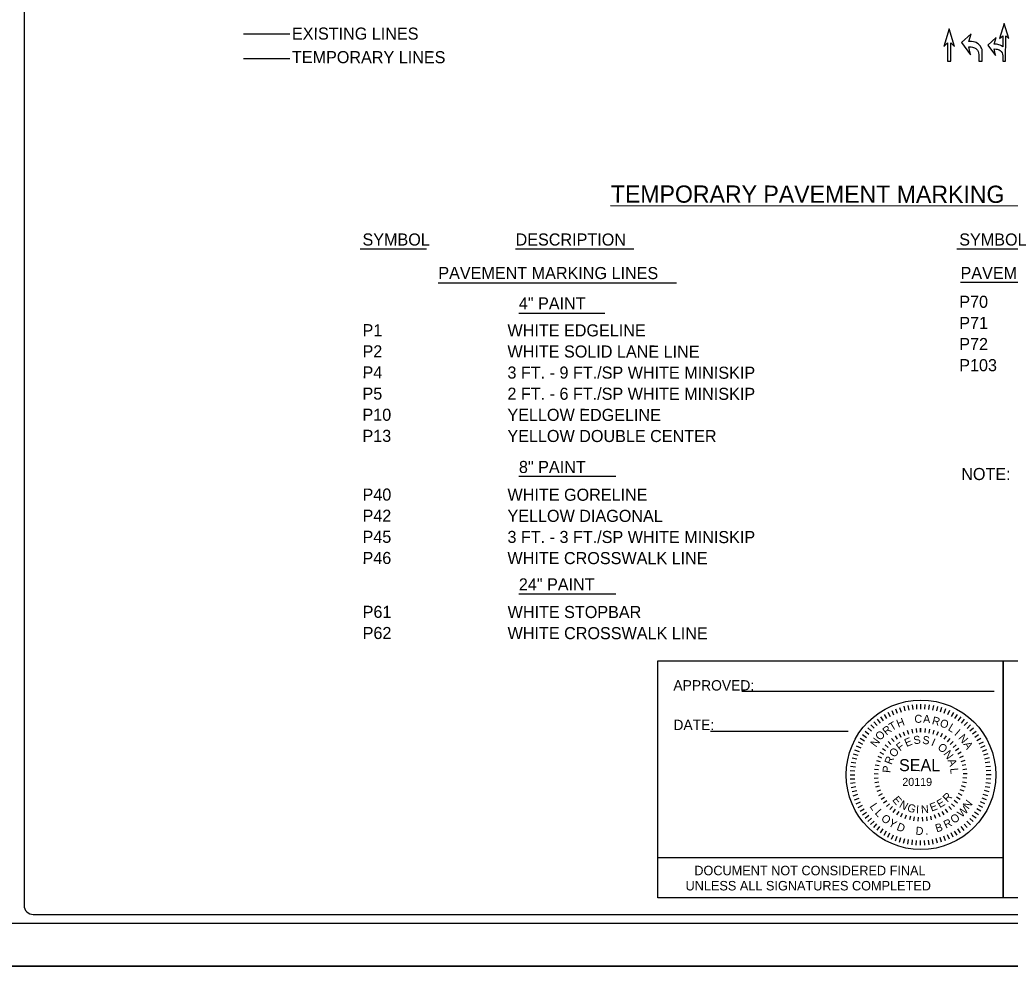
# Model space of a CAD drawing. Extents: x 1403867 to 1405555, y 486423 to 487523.
# Drawn here: x 1404600 to 1405174, y 486423 to 486971 of the extents above; entities that cross this region are included whole.
import ezdxf

# ---------------------------------------------------------------- set-up
doc = ezdxf.new("R2010")
doc.units = 0
for name, color, linetype in [('Default', 7, 'Continuous'), ('DEV BORDER CELL', 7, 'Continuous'), ('Exist Mkg Solid White Crosswalks', 7, 'Continuous'), ('Sheet Plot Border Outside CELL', 7, 'Continuous'), ('Sheet Sticker Exception Certification CELL', 7, 'Continuous')]:
    doc.layers.add(name, color=color, linetype=linetype)

msp = doc.modelspace()

# ---------------------------------------------------------------- linework, layer by layer
at = {"layer": 'Default'}
for p, q in [((1405103.41, 486569.89), (1405104.71, 486567.42)), ((1405105.64, 486570.96), (1405106.77, 486568.42)), ((1405107.92, 486571.91), (1405108.9, 486569.3)), ((1405110.25, 486572.71), (1405111.07, 486570.05)), ((1405112.63, 486573.37), (1405113.29, 486570.67)), ((1405115.04, 486573.89), (1405115.54, 486571.15)), ((1405117.48, 486574.25), (1405117.82, 486571.49)), ((1405119.94, 486574.48), (1405120.11, 486571.7)), ((1405122.41, 486574.55), (1405122.41, 486571.76)), ((1405124.88, 486574.47), (1405124.71, 486571.69)), ((1405127.34, 486574.25), (1405127, 486571.48)), ((1405129.78, 486573.87), (1405129.28, 486571.14)), ((1405132.19, 486573.35), (1405131.53, 486570.65)), ((1405134.57, 486572.69), (1405133.74, 486570.03)), ((1405136.9, 486571.88), (1405135.91, 486569.28)), ((1405139.18, 486570.93), (1405138.04, 486568.39)), ((1405095.3, 486564.29), (1405097.14, 486562.21)), ((1405097.2, 486565.88), (1405098.91, 486563.68)), ((1405099.19, 486567.34), (1405100.77, 486565.04)), ((1405101.26, 486568.67), (1405102.7, 486566.29)), ((1405141.4, 486569.85), (1405140.11, 486567.38)), ((1405143.56, 486568.64), (1405142.11, 486566.25)), ((1405145.63, 486567.29), (1405144.04, 486565)), ((1405147.61, 486565.83), (1405145.89, 486563.64)), ((1405149.51, 486564.24), (1405147.66, 486562.16)), ((1405090.22, 486558.91), (1405092.41, 486557.19)), ((1405091.81, 486560.81), (1405093.89, 486558.96)), ((1405093.5, 486562.6), (1405095.47, 486560.63)), ((1405112.24, 486558.64), (1405113.11, 486556.48)), ((1405114.7, 486559.5), (1405115.36, 486557.27)), ((1405117.22, 486560.12), (1405117.67, 486557.84)), ((1405119.8, 486560.49), (1405120.02, 486558.18)), ((1405122.4, 486560.61), (1405122.4, 486558.29)), ((1405122.4, 486558.29), (1405122.4, 486560.61)), ((1405125, 486560.48), (1405124.77, 486558.18)), ((1405127.57, 486560.11), (1405127.13, 486557.83)), ((1405130.1, 486559.48), (1405129.44, 486557.26)), ((1405132.56, 486558.62), (1405131.68, 486556.47)), ((1405151.3, 486562.55), (1405149.33, 486560.58)), ((1405152.99, 486560.75), (1405150.91, 486558.91)), ((1405154.58, 486558.85), (1405152.38, 486557.14)), ((1405086.2, 486552.7), (1405088.67, 486551.41)), ((1405087.41, 486554.86), (1405089.8, 486553.41)), ((1405088.76, 486556.93), (1405091.05, 486555.34)), ((1405103.58, 486552.97), (1405105.2, 486551.3)), ((1405105.52, 486554.69), (1405106.98, 486552.88)), ((1405107.63, 486556.22), (1405108.9, 486554.28)), ((1405109.88, 486557.54), (1405110.95, 486555.48)), ((1405134.92, 486557.52), (1405133.84, 486555.46)), ((1405137.16, 486556.2), (1405135.89, 486554.25)), ((1405139.27, 486554.66), (1405137.81, 486552.85)), ((1405141.21, 486552.93), (1405139.59, 486551.27)), ((1405156.04, 486556.86), (1405153.74, 486555.28)), ((1405157.38, 486554.79), (1405154.99, 486553.35)), ((1405158.59, 486552.64), (1405156.12, 486551.34)), ((1405084.17, 486548.2), (1405086.77, 486547.21)), ((1405085.12, 486550.48), (1405087.66, 486549.34)), ((1405100.22, 486549), (1405102.13, 486547.68)), ((1405101.8, 486551.07), (1405103.57, 486549.57)), ((1405142.98, 486551.03), (1405141.21, 486549.53)), ((1405144.56, 486548.96), (1405142.65, 486547.64)), ((1405159.66, 486550.41), (1405157.12, 486549.28)), ((1405160.61, 486548.13), (1405158, 486547.15)), ((1405082.69, 486543.49), (1405085.4, 486542.83)), ((1405083.36, 486545.87), (1405086.02, 486545.04)), ((1405096.76, 486542.02), (1405098.97, 486541.31)), ((1405097.69, 486544.46), (1405099.81, 486543.53)), ((1405098.84, 486546.79), (1405100.87, 486545.66)), ((1405145.93, 486546.75), (1405143.9, 486545.62)), ((1405147.08, 486544.41), (1405144.95, 486543.49)), ((1405148, 486541.97), (1405145.79, 486541.26)), ((1405161.41, 486545.8), (1405158.75, 486544.97)), ((1405162.07, 486543.42), (1405159.37, 486542.76)), ((1405081.58, 486536.18), (1405084.36, 486536.01)), ((1405081.8, 486538.64), (1405084.57, 486538.3)), ((1405082.17, 486541.08), (1405084.91, 486540.58)), ((1405095.63, 486536.95), (1405097.94, 486536.67)), ((1405096.07, 486539.51), (1405098.34, 486539.01)), ((1405148.69, 486539.46), (1405146.42, 486538.97)), ((1405149.12, 486536.9), (1405146.82, 486536.62)), ((1405162.59, 486541), (1405159.85, 486540.51)), ((1405162.96, 486538.56), (1405160.19, 486538.23)), ((1405163.18, 486536.11), (1405160.4, 486535.94)), ((1405081.5, 486533.71), (1405084.29, 486533.71)), ((1405081.57, 486531.24), (1405084.35, 486531.41)), ((1405095.44, 486534.35), (1405097.76, 486534.29)), ((1405095.5, 486531.75), (1405097.82, 486531.91)), ((1405149.24, 486531.7), (1405146.93, 486531.87)), ((1405149.31, 486534.3), (1405146.99, 486534.24)), ((1405163.17, 486531.17), (1405160.39, 486531.34)), ((1405163.25, 486533.64), (1405160.46, 486533.64)), ((1405081.79, 486528.78), (1405084.56, 486529.12)), ((1405082.16, 486526.34), (1405084.9, 486526.84)), ((1405082.68, 486523.93), (1405085.38, 486524.59)), ((1405095.82, 486529.16), (1405098.1, 486529.55)), ((1405096.37, 486526.62), (1405098.61, 486527.23)), ((1405097.18, 486524.14), (1405099.35, 486524.96)), ((1405147.56, 486524.1), (1405145.39, 486524.92)), ((1405148.36, 486526.57), (1405146.12, 486527.18)), ((1405146.65, 486529.59), (1405148.94, 486529.2)), ((1405162.06, 486523.86), (1405159.35, 486524.52)), ((1405162.58, 486526.27), (1405159.84, 486526.77)), ((1405162.95, 486528.71), (1405160.18, 486529.05)), ((1405083.34, 486521.55), (1405086, 486522.37)), ((1405084.14, 486519.22), (1405086.75, 486520.2)), ((1405098.22, 486521.76), (1405100.3, 486522.79)), ((1405099.48, 486519.48), (1405101.45, 486520.7)), ((1405100.95, 486517.34), (1405102.8, 486518.74)), ((1405143.77, 486517.3), (1405141.92, 486518.71)), ((1405145.25, 486519.44), (1405143.28, 486520.66)), ((1405146.51, 486521.71), (1405144.43, 486522.75)), ((1405160.58, 486519.15), (1405157.98, 486520.14)), ((1405161.39, 486521.48), (1405158.73, 486522.31)), ((1405085.09, 486516.93), (1405087.63, 486518.07)), ((1405086.16, 486514.71), (1405088.63, 486516.01)), ((1405087.37, 486512.56), (1405089.76, 486514)), ((1405102.63, 486515.35), (1405104.33, 486516.92)), ((1405104.49, 486513.53), (1405106.03, 486515.26)), ((1405106.52, 486511.9), (1405107.89, 486513.77)), ((1405108.69, 486510.47), (1405109.88, 486512.47)), ((1405138.19, 486511.87), (1405136.83, 486513.74)), ((1405140.22, 486513.49), (1405138.68, 486515.23)), ((1405142.08, 486515.31), (1405140.39, 486516.89)), ((1405157.34, 486512.49), (1405154.95, 486513.94)), ((1405158.55, 486514.65), (1405156.08, 486515.94)), ((1405159.63, 486516.87), (1405157.09, 486518.01)), ((1405088.71, 486510.49), (1405091.01, 486512.07)), ((1405090.17, 486508.5), (1405092.37, 486510.21)), ((1405091.76, 486506.6), (1405093.84, 486508.44)), ((1405093.45, 486504.8), (1405095.42, 486506.77)), ((1405111, 486509.26), (1405111.98, 486511.36)), ((1405113.41, 486508.27), (1405114.19, 486510.46)), ((1405116.45, 486509.78), (1405115.89, 486507.52)), ((1405118.46, 486507.02), (1405118.79, 486509.32)), ((1405121.05, 486506.77), (1405121.16, 486509.08)), ((1405123.65, 486506.76), (1405123.54, 486509.08)), ((1405126.24, 486507.01), (1405125.91, 486509.31)), ((1405128.8, 486507.51), (1405128.24, 486509.77)), ((1405131.29, 486508.25), (1405130.52, 486510.45)), ((1405133.7, 486509.23), (1405132.73, 486511.34)), ((1405136.01, 486510.44), (1405134.83, 486512.45)), ((1405151.25, 486504.75), (1405149.28, 486506.72)), ((1405152.94, 486506.54), (1405150.86, 486508.39)), ((1405154.53, 486508.44), (1405152.34, 486510.16)), ((1405155.99, 486510.42), (1405153.7, 486512.01)), ((1405095.24, 486503.1), (1405097.09, 486505.19)), ((1405097.14, 486501.52), (1405098.86, 486503.71)), ((1405099.12, 486500.06), (1405100.71, 486502.35)), ((1405101.19, 486498.71), (1405102.64, 486501.1)), ((1405143.49, 486498.67), (1405142.05, 486501.06)), ((1405145.56, 486500.01), (1405143.98, 486502.31)), ((1405147.55, 486501.47), (1405145.84, 486503.67)), ((1405149.45, 486503.06), (1405147.61, 486505.14)), ((1405103.35, 486497.5), (1405104.64, 486499.97)), ((1405105.57, 486496.42), (1405106.71, 486498.96)), ((1405107.85, 486495.47), (1405108.84, 486498.07)), ((1405110.18, 486494.66), (1405111.01, 486497.32)), ((1405112.56, 486493.99), (1405113.22, 486496.7)), ((1405114.97, 486493.47), (1405115.47, 486496.21)), ((1405117.41, 486493.1), (1405117.75, 486495.87)), ((1405119.87, 486492.88), (1405120.04, 486495.66)), ((1405122.34, 486492.8), (1405122.34, 486495.59)), ((1405124.81, 486492.87), (1405124.64, 486495.65)), ((1405127.26, 486493.09), (1405126.93, 486495.86)), ((1405129.71, 486493.46), (1405129.21, 486496.2)), ((1405132.12, 486493.98), (1405131.46, 486496.68)), ((1405134.5, 486494.64), (1405133.68, 486497.3)), ((1405136.83, 486495.44), (1405135.85, 486498.05)), ((1405139.11, 486496.39), (1405137.98, 486498.93)), ((1405141.34, 486497.46), (1405140.04, 486499.93))]:
    msp.add_line(p, q, dxfattribs=at)
at = {"layer": 'DEV BORDER CELL'}
for p, q in [((1404602.84, 487487.44), (1404602.84, 486458)), ((1404729.97, 486948.81), (1404756.76, 486948.81)), ((1404942.59, 486863.67), (1405185.61, 486863.5)), ((1404797.58, 486838.56), (1404836.13, 486838.56)), ((1404887.65, 486838.56), (1404956.19, 486838.56)), ((1405143.43, 486838.56), (1405181.98, 486838.56)), ((1404842.89, 486818.79), (1404980.95, 486818.79)), ((1405145.53, 486819.16), (1405298.37, 486819.16)), ((1404889.55, 486801.23), (1404939.48, 486801.23)), ((1404889.61, 486706.7), (1404945.85, 486706.7)), ((1404889.56, 486638.63), (1404945.8, 486638.63)), ((1405018.72, 486582.09), (1405165.06, 486582.09)), ((1405170.21, 486576.27), (1405170.21, 486462.27)), ((1405000.61, 486559.02), (1405080.4, 486559.02)), ((1404608.13, 486452.72), (1405520.08, 486452.72)), ((1404040.64, 486447.72), (1405520.08, 486447.72))]:
    msp.add_line(p, q, dxfattribs=at)
for points in [[(1405135.76, 486955.9), (1405137.93, 486957.9), (1405137.92, 486947.24), (1405139.92, 486947.23), (1405139.93, 486957.9), (1405142.09, 486955.9), (1405138.93, 486966.07)], [(1405171.69, 486947.23), (1405171.7, 486962.1), (1405173.56, 486960.38), (1405170.85, 486969.1), (1405168.13, 486960.38), (1405169.99, 486962.1), (1405169.98, 486955.63), (1405169.2, 486956.26), (1405168.59, 486956.61), (1405167.82, 486956.89), (1405167.19, 486957.02), (1405166.4, 486957.14), (1405164.98, 486957.1), (1405166.13, 486960.96), (1405161.27, 486956.53), (1405165.83, 486950.52), (1405164.98, 486954.38), (1405166.09, 486954.36), (1405166.75, 486954.33), (1405167.41, 486954.17), (1405167.99, 486953.86), (1405168.56, 486953.54), (1405169.14, 486952.93), (1405169.58, 486952.19), (1405169.85, 486951.39), (1405169.99, 486950.49), (1405169.98, 486947.23)], [(1405156.16, 486947.23), (1405158.16, 486947.23), (1405158.16, 486952.4), (1405158.11, 486953.35), (1405157.99, 486954.08), (1405157.74, 486954.86), (1405157.39, 486955.53), (1405157.05, 486956.03), (1405156.48, 486956.69), (1405155.97, 486957.13), (1405155.38, 486957.61), (1405154.59, 486958.08), (1405153.96, 486958.33), (1405153.11, 486958.58), (1405151.94, 486958.74), (1405150.34, 486958.74), (1405151.67, 486963.24), (1405146, 486958.08), (1405151.33, 486951.07), (1405150.33, 486955.57), (1405151.67, 486955.57), (1405152.41, 486955.53), (1405153.11, 486955.34), (1405153.64, 486955.09), (1405154.33, 486954.68), (1405154.81, 486954.3), (1405155.34, 486953.64), (1405155.72, 486952.88), (1405156, 486952.13), (1405156.16, 486951.07)], [(1404970.17, 486599.77), (1405170.21, 486599.77), (1405170.21, 486462.27), (1404970.17, 486462.27)], [(1405170.21, 486599.77), (1405284.21, 486599.77), (1405284.21, 486462.27), (1405170.21, 486462.27)]]:
    msp.add_lwpolyline(points, close=True, dxfattribs=at)
msp.add_circle((1405122.61, 486533.68), 43.34, dxfattribs=at)
msp.add_arc((1404608.12, 486458), 5.29, 180, 270.00285, dxfattribs=at)
at = {"layer": 'Exist Mkg Solid White Crosswalks'}
msp.add_line((1404729.97, 486963.21), (1404756.76, 486963.21), dxfattribs=at)
at = {"layer": 'Sheet Plot Border Outside CELL'}
for points in [[(1403867.36, 486422.72), (1403867.36, 487522.72), (1405555.36, 487522.72), (1405555.36, 486422.72)], [(1403867.36, 487522.72), (1405555.36, 487522.72), (1405555.36, 486422.72), (1403867.36, 486422.72)], [(1403867.36, 486422.72), (1405555.36, 486422.72), (1405555.36, 487522.72), (1403867.36, 487522.72)]]:
    msp.add_lwpolyline(points, close=True, dxfattribs=at)
at = {"layer": 'Sheet Sticker Exception Certification CELL'}
for p, q in [((1404970.17, 486462.27), (1404970.17, 486485.77)), ((1404970.17, 486485.77), (1405170.21, 486485.77)), ((1405170.21, 486485.76), (1405170.21, 486462.26)), ((1405170.21, 486462.27), (1404970.17, 486462.27))]:
    msp.add_line(p, q, dxfattribs=at)

# ---------------------------------------------------------------- texts
at = {"layer": 'Default'}
for s, height, rotation, p in [('T', 4.64, 30.44658, (1405105.72, 486558.93)), ('H', 4.64, 21.01464, (1405109.45, 486560.94)), ('C', 4.64, 357.30395, (1405118.69, 486563.92)), ('A', 4.64, 357.30395, (1405123.76, 486563.82)), ('R', 4.64, 345.29464, (1405128.68, 486563.13)), ('O', 4.64, 342.23783, (1405133.17, 486561.79)), ('O', 4.64, 51.66428, (1405099.23, 486553.21)), ('R', 4.64, 38.60755, (1405102.59, 486556.33)), ('L', 4.64, 329.10154, (1405137.89, 486559.72)), ('I', 4.64, 319.52607, (1405141.63, 486557.02)), ('N', 4.64, 53.62371, (1405096.56, 486549.29)), ('F', 4.64, 38.1876, (1405110.49, 486547.11)), ('E', 4.64, 22.89135, (1405114.2, 486549.73)), ('S', 4.64, 7.5951, (1405118.56, 486551.32)), ('S', 4.64, 352.29886, (1405123.2, 486551.7)), ('I', 4.64, 337.00261, (1405128.13, 486550.7)), ('N', 4.64, 310.23161, (1405143.95, 486554.83)), ('O', 4.64, 53.48384, (1405107.4, 486543.37)), ('O', 4.64, 321.70637, (1405131.87, 486548.89)), ('N', 4.64, 306.41012, (1405135.44, 486545.77)), ('A', 4.64, 300.46408, (1405147.01, 486551.4)), ('R', 4.64, 68.78009, (1405105.56, 486539.2)), ('SEAL', 6.965, 359.94698, (1405109.9, 486535.78)), ('A', 4.64, 291.11388, (1405137.98, 486541.97)), ('P', 4.64, 84.07634, (1405104.85, 486534.61)), ('L', 4.64, 275.81763, (1405139.48, 486537.38)), ('20119', 4.64, 359.94698, (1405111.79, 486527.24)), ('E', 4.64, 310.01707, (1405105.73, 486518.95)), ('N', 4.64, 330.87215, (1405109.62, 486515.08)), ('E', 4.64, 30.74079, (1405133.48, 486514.26)), ('R', 4.64, 44.51187, (1405137.9, 486517.49)), ('N', 4.64, 52.15404, (1405150.12, 486513.29)), ('L', 4.64, 303.882, (1405092.68, 486515.33)), ('L', 4.64, 311.95381, (1405095.55, 486511.34)), ('G', 4.64, 339.63838, (1405114.16, 486512.9)), ('I', 4.64, 357.73318, (1405119.69, 486511.41)), ('N', 4.64, 5.36284, (1405122.84, 486511.25)), ('E', 4.64, 20.7549, (1405128.72, 486512.28)), ('W', 4.64, 43.27141, (1405146.22, 486508.62)), ('O', 4.64, 320.59656, (1405099.07, 486507.68)), ('Y', 4.64, 329.26915, (1405103.29, 486504.44)), ('R', 4.64, 25.56616, (1405137.04, 486502.38)), ('O', 4.64, 34.38878, (1405141.65, 486505.14)), ('D', 4.64, 338.24163, (1405108.12, 486501.81)), ('D', 4.64, 356.03694, (1405119.4, 486498.98)), ('B', 4.64, 16.5636, (1405131.68, 486500.27)), ('.', 4.64, 3.77928, (1405125.25, 486498.94))]:
    msp.add_text(s, height=height, rotation=rotation, dxfattribs=at).set_placement(p)
at = {"layer": 'DEV BORDER CELL'}
for s, height, p in [('EXISTING LINES', 7, (1404758.06, 486959.84)), ('TEMPORARY LINES', 7, (1404758.06, 486946.18)), ('TEMPORARY PAVEMENT MARKING ', 10, (1404942.88, 486865.32)), ('SYMBOL', 7, (1404798.94, 486840.47)), ('DESCRIPTION', 7, (1404887.66, 486840.47)), ('SYMBOL', 7, (1405144.79, 486840.47)), ('PAVEMENT MARKING LINES', 7, (1404842.89, 486821.08)), ('PAVEMENT MARKING SYMBOLS', 7, (1405145.53, 486821.08)), ('P70', 7, (1405144.81, 486804.36)), ('4" PAINT', 7, (1404889.55, 486803.44)), ('P1', 7, (1404798.97, 486787.88)), ('WHITE EDGELINE', 7, (1404882.97, 486787.82)), ('P71', 7, (1405144.8, 486792.11)), ('P2', 7, (1404798.96, 486775.63)), ('WHITE SOLID LANE LINE', 7, (1404882.96, 486775.57)), ('P72', 7, (1405144.79, 486779.87)), ('P103', 7, (1405144.78, 486767.62)), ('P4', 7, (1404798.95, 486763.39)), ('3 FT. - 9 FT./SP WHITE MINISKIP', 7, (1404882.95, 486763.33)), ('P5', 7, (1404798.94, 486751.14)), ('2 FT. - 6 FT./SP WHITE MINISKIP', 7, (1404882.94, 486751.08)), ('P10', 7, (1404798.93, 486738.89)), ('YELLOW EDGELINE ', 7, (1404882.94, 486738.83)), ('P13', 7, (1404798.93, 486726.65)), ('YELLOW DOUBLE CENTER ', 7, (1404882.93, 486726.59)), ('8" PAINT', 7, (1404889.61, 486708.62)), ('NOTE:', 7, (1405145.95, 486704.53)), ('P40', 7, (1404798.98, 486692.61)), ('WHITE GORELINE', 7, (1404882.98, 486692.55)), ('P42', 7, (1404798.97, 486680.36)), ('YELLOW DIAGONAL', 7, (1404882.97, 486680.3)), ('P45', 7, (1404798.96, 486668.12)), ('3 FT. - 3 FT./SP WHITE MINISKIP', 7, (1404882.96, 486668.06)), ('P46', 7, (1404798.95, 486655.87)), ('WHITE CROSSWALK LINE', 7, (1404882.95, 486655.81)), ('24" PAINT', 7, (1404889.56, 486640.55)), ('P61', 7, (1404799.04, 486624.62)), ('WHITE STOPBAR', 7, (1404883.04, 486624.56)), ('P62', 7, (1404799.03, 486612.37)), ('WHITE CROSSWALK LINE', 7, (1404883.03, 486612.31))]:
    msp.add_text(s, height=height, rotation=359.9598, dxfattribs=at).set_placement(p)
for s, p in [('APPROVED:  ', (1404979.14, 486582.52)), ('DATE:  ', (1404979.14, 486559.61))]:
    msp.add_text(s, height=6, dxfattribs=at).set_placement(p)
at = {"layer": 'Sheet Sticker Exception Certification CELL'}
for s, p in [('DOCUMENT NOT CONSIDERED FINAL', (1404991.25, 486475.43)), ('UNLESS ALL SIGNATURES COMPLETED', (1404986.17, 486466.63))]:
    msp.add_text(s, height=5.5, dxfattribs=at).set_placement(p)

doc.saveas('drawing.dxf')
